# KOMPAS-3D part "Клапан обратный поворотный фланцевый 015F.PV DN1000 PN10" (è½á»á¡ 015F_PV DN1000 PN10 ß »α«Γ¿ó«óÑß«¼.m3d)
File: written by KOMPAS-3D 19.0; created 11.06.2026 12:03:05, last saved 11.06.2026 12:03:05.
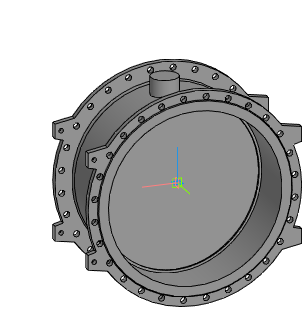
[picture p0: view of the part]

Document properties: Автор: Энергия; Полное имя файла: Z:\3.Личные\kachalov\001_3d для проектировщиков\5.5 Тип 015F.PV Клапан обратный поворотный с двумя эксцентриками\_stp_Клапан 015F.PV DN300-DN1200 с противовесом\Клапан 015F_PV DN1000 PN10 с противовесом.m3d

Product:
- Part/product: Клапан обратный поворотный фланцевый 015F.PV DN1000 PN10

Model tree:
1. Операция без истории:1
2. Сплайн:1
     Координата Y = 30; Координата Z = 500; Вес = 1; Координата X = 1000; Координата Y = 161.652; Координата Z = 500; Вес = 0.333333; Координата X = 1000; Координата Y = 161.652; Координата Z = -500; Вес = 0.333333; Координата Y = 30; Координата Z = -500; Вес = 1; Координата X = -1000; Координата Y = -101.652; Координата Z = -500; Вес = 0.333333; Координата X = -1000; Координата Y = -101.652; Координата Z = 500; Вес = 0.333333; Порядок = 4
